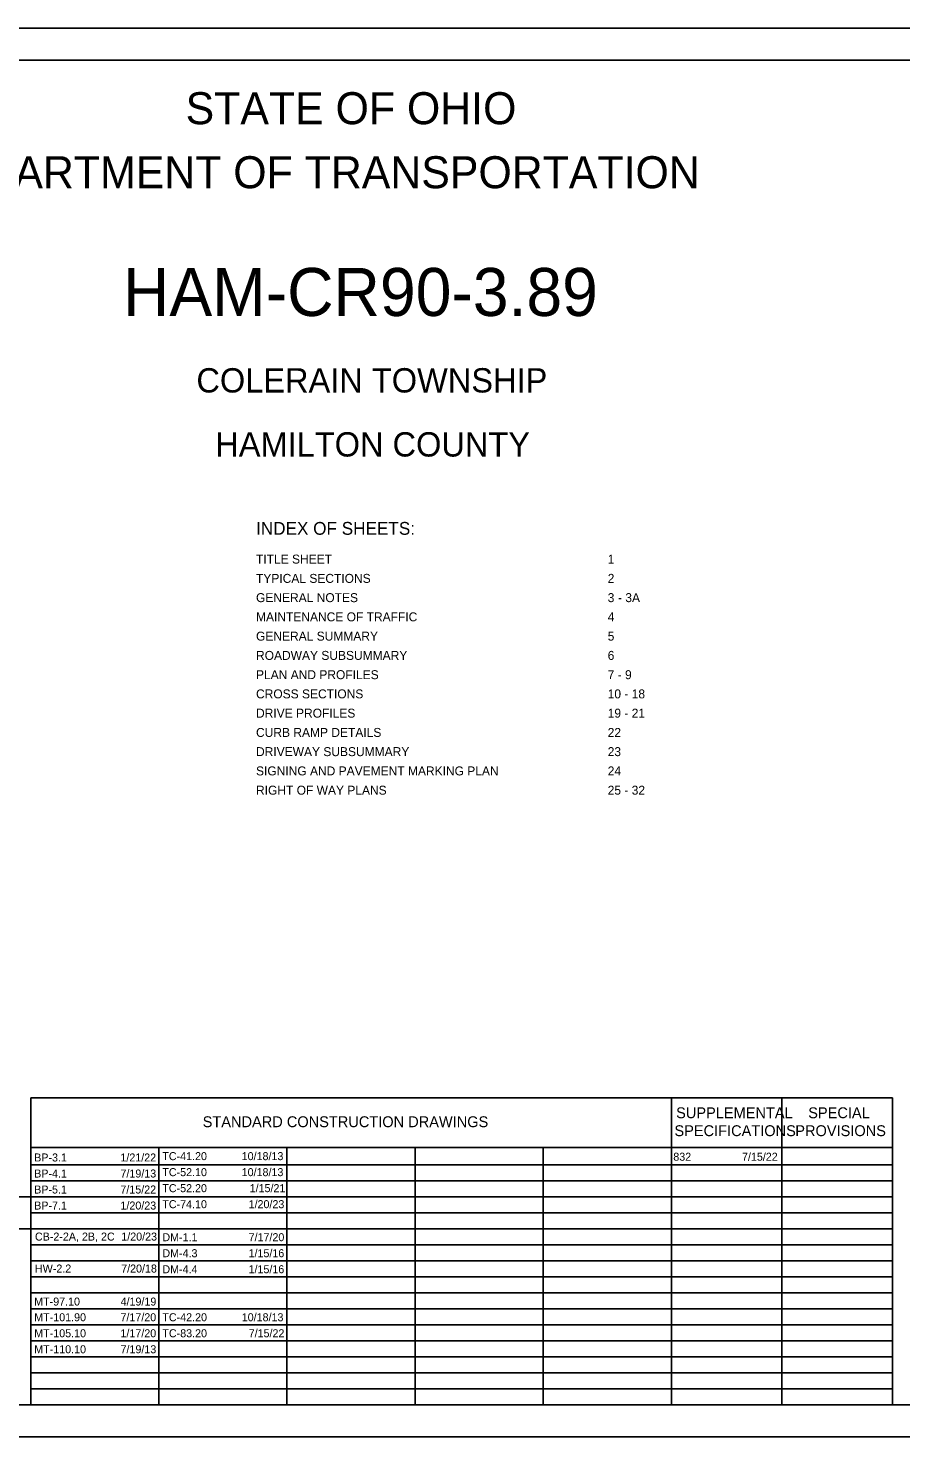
# Model space of a CAD drawing. Extents: x 0 to 69.5, y -4.5 to 22.
# Drawn here: x 11.51 to 25.13, y 0 to 22 of the extents above; entities that cross this region are included whole.
import ezdxf

# ---------------------------------------------------------------- set-up
doc = ezdxf.new("R2010")
doc.units = 0
for name, color, linetype in [('RD_P_Text', 7, 'Continuous'), ('SH_Border', 7, 'Continuous'), ('SH_Data', 7, 'Continuous'), ('SH_Text', 7, 'Continuous')]:
    doc.layers.add(name, color=color, linetype=linetype)

msp = doc.modelspace()

# ---------------------------------------------------------------- linework, layer by layer
at = {"layer": 'SH_Border'}
msp.add_lwpolyline([(1.5, 21.5), (33.5, 21.5), (33.5, 0.5), (1.5, 0.5)], close=True, dxfattribs=at)
at = {"layer": 'SH_Data'}
for p, q in [((11.55, 0.5), (11.55, 5.292)), ((11.55, 5.292), (25, 5.292)), ((21.55, 0.5), (21.55, 5.292)), ((23.275, 0.5), (23.275, 5.292)), ((25, 0.5), (25, 5.292)), ((11.55, 4.521), (25, 4.521)), ((13.55, 0.5), (13.55, 4.521)), ((15.55, 0.5), (15.55, 4.521)), ((17.55, 0.5), (17.55, 4.521)), ((19.55, 0.5), (19.55, 4.521)), ((11.55, 4.25), (25, 4.25)), ((11.55, 4), (25, 4)), ((8.75, 3.75), (11.55, 3.75)), ((11.55, 3.75), (25, 3.75)), ((11.55, 3.5), (25, 3.5)), ((8.75, 3.25), (11.55, 3.25)), ((11.55, 3.25), (25, 3.25)), ((11.55, 3), (25, 3)), ((11.55, 2.75), (25, 2.75)), ((11.55, 2.5), (25, 2.5)), ((11.55, 2.25), (25, 2.25)), ((11.55, 2), (25, 2)), ((11.55, 1.75), (25, 1.75)), ((11.55, 1.5), (25, 1.5)), ((11.55, 1.25), (25, 1.25)), ((11.55, 1), (25, 1)), ((11.55, 0.75), (25, 0.75))]:
    msp.add_line(p, q, dxfattribs=at)
msp.add_lwpolyline([(0, 0), (34, 0), (34, 22), (0, 22)], close=True, dxfattribs=at)

# ---------------------------------------------------------------- texts
at = {"layer": 'RD_P_Text'}
for s, p in [('BP-3.1', (11.604, 4.3)), ('1/21/22', (12.95, 4.3)), ('TC-41.20', (13.604, 4.321)), ('10/18/13', (14.843, 4.321)), ('832', (21.58, 4.312)), ('7/15/22', (22.652, 4.312)), ('7/19/13', (12.951, 4.05)), ('TC-52.10', (13.604, 4.071)), ('10/18/13', (14.843, 4.071)), ('BP-4.1', (11.604, 4.05)), ('BP-5.1', (11.604, 3.8)), ('7/15/22', (12.95, 3.8)), ('TC-52.20', (13.604, 3.821)), ('1/15/21', (14.967, 3.821)), ('BP-7.1', (11.604, 3.55)), ('1/20/23', (12.951, 3.55)), ('TC-74.10', (13.604, 3.571)), ('1/20/23', (14.951, 3.571)), ('CB-2-2A, 2B, 2C', (11.616, 3.065)), ('1/20/23', (12.964, 3.065)), ('DM-1.1', (13.605, 3.055)), ('7/17/20', (14.951, 3.055)), ('DM-4.3', (13.605, 2.805)), ('1/15/16', (14.95, 2.805)), ('HW-2.2', (11.616, 2.566)), ('7/20/18', (12.962, 2.566)), ('DM-4.4', (13.605, 2.555)), ('1/15/16', (14.95, 2.555)), ('MT-97.10', (11.604, 2.05)), ('4/19/19', (12.953, 2.05)), ('MT-101.90', (11.605, 1.805)), ('7/17/20', (12.951, 1.805)), ('TC-42.20', (13.605, 1.805)), ('10/18/13', (14.844, 1.805)), ('MT-105.10', (11.605, 1.555)), ('1/17/20', (12.951, 1.555)), ('TC-83.20', (13.605, 1.555)), ('7/15/22', (14.952, 1.555)), ('MT-110.10', (11.605, 1.305)), ('7/19/13', (12.952, 1.305))]:
    msp.add_text(s, height=0.125, dxfattribs=at).set_placement(p)
at = {"layer": 'SH_Data'}
for s, height, p in [('INDEX OF SHEETS:', 0.2, (15.067, 14.088)), ('TITLE SHEET', 0.14, (15.067, 13.638)), ('1', 0.14, (20.556, 13.638)), ('TYPICAL SECTIONS', 0.14, (15.067, 13.337)), ('2', 0.14, (20.556, 13.337)), ('GENERAL NOTES', 0.14, (15.067, 13.036)), ('3', 0.14, (20.556, 13.036)), (' - 3A', 0.14, (20.665, 13.036)), ('MAINTENANCE OF TRAFFIC', 0.14, (15.067, 12.736)), ('4', 0.14, (20.556, 12.736)), ('GENERAL SUMMARY', 0.14, (15.067, 12.435)), ('5', 0.14, (20.556, 12.435)), ('ROADWAY SUBSUMMARY', 0.14, (15.067, 12.134)), ('6', 0.14, (20.556, 12.134)), ('PLAN AND PROFILES', 0.14, (15.067, 11.833)), ('7 - 9', 0.14, (20.556, 11.833)), ('CROSS SECTIONS', 0.14, (15.067, 11.533)), ('10 - 18', 0.14, (20.556, 11.533)), ('DRIVE PROFILES', 0.14, (15.067, 11.232)), ('19 - 21', 0.14, (20.556, 11.232)), ('CURB RAMP DETAILS', 0.14, (15.067, 10.931)), ('22', 0.14, (20.556, 10.931)), ('DRIVEWAY SUBSUMMARY', 0.14, (15.067, 10.631)), ('23', 0.14, (20.556, 10.631)), ('SIGNING AND PAVEMENT MARKING PLAN', 0.14, (15.067, 10.33)), ('24', 0.14, (20.556, 10.33)), ('RIGHT OF WAY PLANS', 0.14, (15.067, 10.029)), ('25 - 32', 0.14, (20.556, 10.029)), ('SUPPLEMENTAL', 0.17, (21.624, 4.976)), ('SPECIAL', 0.17, (23.686, 4.976)), ('STANDARD CONSTRUCTION DRAWINGS', 0.17, (14.234, 4.836)), ('SPECIFICATIONS', 0.17, (21.598, 4.696)), ('PROVISIONS', 0.17, (23.484, 4.696))]:
    msp.add_text(s, height=height, dxfattribs=at).set_placement(p)
at = {"layer": 'SH_Text'}
for s, height, p in [('STATE OF OHIO', 0.5, (13.968, 20.5)), ('DEPARTMENT OF TRANSPORTATION', 0.5, (9.92, 19.5)), ('HAM-CR90-3.89', 0.75, (12.99, 17.505)), ('COLERAIN TOWNSHIP', 0.38, (14.136, 16.31)), ('HAMILTON COUNTY', 0.38, (14.431, 15.31))]:
    msp.add_text(s, height=height, dxfattribs=at).set_placement(p)

doc.saveas('drawing.dxf')
